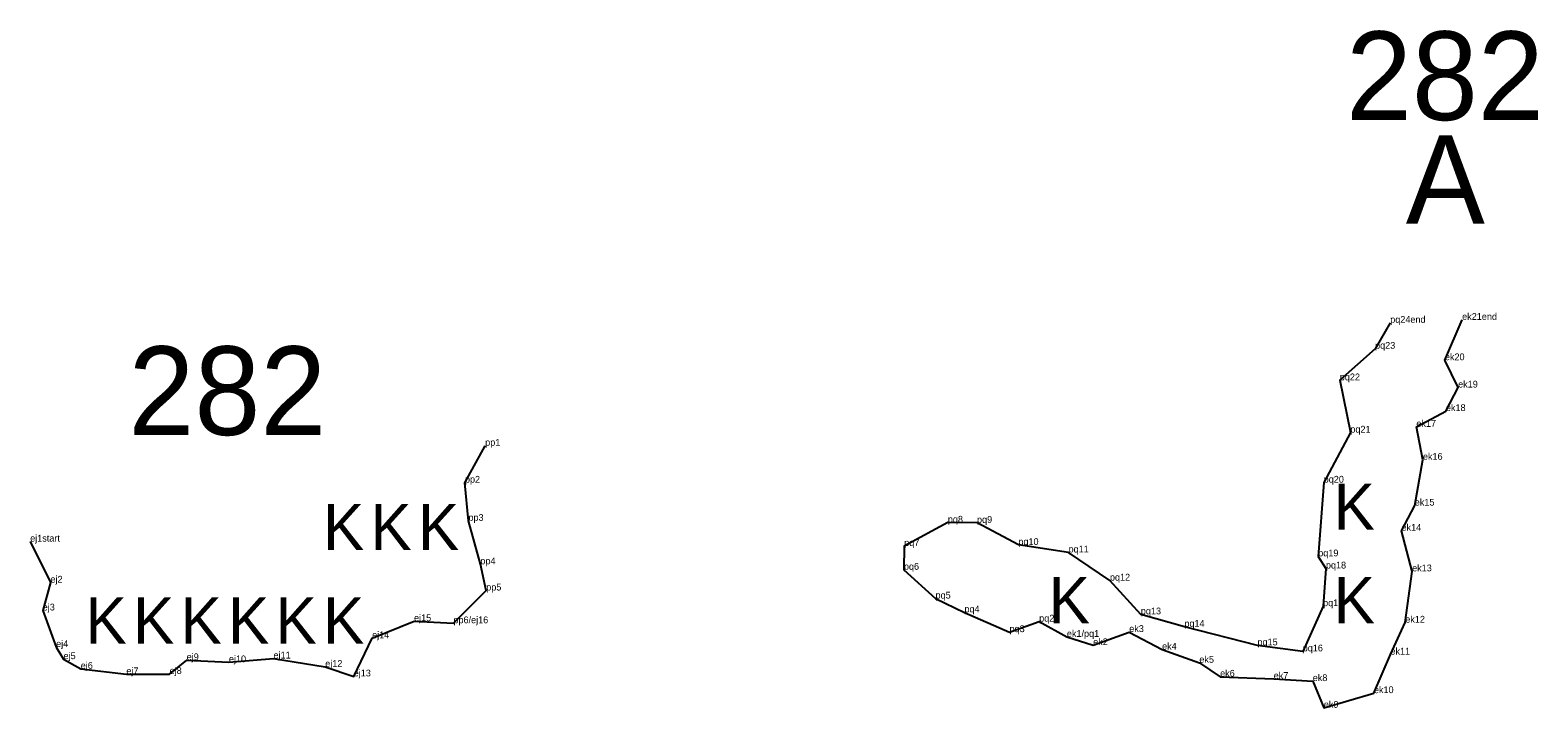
# Model space of a CAD drawing. Extents: x 2072529 to 2268812, y 436423 to 470008.
# Drawn here: x 2242590 to 2243701, y 441089 to 441588 of the extents above; entities that cross this region are included whole.
import ezdxf

# ---------------------------------------------------------------- set-up
doc = ezdxf.new("R2010")
doc.units = 0
for name, color, linetype in [('Old_Level_20', 7, 'Continuous'), ('Old_Level_52', 7, 'Continuous'), ('Old_Level_55', 7, 'Continuous'), ('Old_Level_60', 7, 'Continuous'), ('Old_Level_62', 7, 'Continuous')]:
    doc.layers.add(name, color=color, linetype=linetype)

msp = doc.modelspace()

# ---------------------------------------------------------------- linework, layer by layer
at = {"layer": 'Old_Level_20'}
for p, q in [((2243592.525, 441372.572), (2243592.525, 441372.572)), ((2243645.53, 441374.726), (2243645.53, 441374.726)), ((2243581.368, 441353.449), (2243581.368, 441353.449)), ((2243632.814, 441344.961), (2243632.814, 441344.961)), ((2243555.368, 441330.16), (2243555.368, 441330.16)), ((2243642.57, 441324.819), (2243642.57, 441324.819)), ((2243633.553, 441307.474), (2243633.553, 441307.474)), ((2243563.152, 441291.577), (2243563.152, 441291.577)), ((2243611.773, 441295.836), (2243611.773, 441295.836)), ((2242925.614, 441281.918), (2242925.614, 441281.918)), ((2243616.622, 441271.518), (2243616.622, 441271.518)), ((2242910.696, 441254.655), (2242910.696, 441254.655)), ((2243543.504, 441254.679), (2243543.504, 441254.679)), ((2243610.634, 441237.723), (2243610.634, 441237.723)), ((2242913.263, 441226.493), (2242913.263, 441226.493)), ((2243266.538, 441225.164), (2243266.538, 441225.164)), ((2243288.046, 441224.991), (2243288.046, 441224.991)), ((2242590.314, 441211.19), (2242590.314, 441211.19)), ((2243318.524, 441208.688), (2243318.524, 441208.688)), ((2243600.837, 441219.164), (2243600.837, 441219.164)), ((2243234.395, 441207.91), (2243234.395, 441207.91)), ((2243355.504, 441203.173), (2243355.504, 441203.173)), ((2243539.461, 441200.297), (2243539.461, 441200.297)), ((2242922.074, 441194.465), (2242922.074, 441194.465)), ((2243234.158, 441190.406), (2243234.158, 441190.406)), ((2243545.129, 441191.353), (2243545.129, 441191.353)), ((2243608.673, 441189.245), (2243608.673, 441189.245)), ((2242605.312, 441180.928), (2242605.312, 441180.928)), ((2243385.968, 441182.446), (2243385.968, 441182.446)), ((2242926.383, 441175.137), (2242926.383, 441175.137)), ((2243257.476, 441169.186), (2243257.476, 441169.186)), ((2242599.552, 441160.387), (2242599.552, 441160.387)), ((2243278.798, 441159.002), (2243278.798, 441159.002)), ((2243408.754, 441157.537), (2243408.754, 441157.537)), ((2243543.067, 441163.582), (2243543.067, 441163.582)), ((2242873.198, 441152.511), (2242873.198, 441152.511)), ((2242902.221, 441150.97), (2242902.221, 441150.97)), ((2243312.007, 441144.425), (2243312.007, 441144.425)), ((2243333.847, 441152.189), (2243333.847, 441152.189)), ((2243400.204, 441144.505), (2243400.204, 441144.505)), ((2243440.843, 441148.363), (2243440.843, 441148.363)), ((2243603.621, 441151.408), (2243603.621, 441151.408)), ((2242609.445, 441133.415), (2242609.445, 441133.415)), ((2242842.325, 441139.889), (2242842.325, 441139.889)), ((2243354.261, 441140.909), (2243354.261, 441140.909)), ((2243373.638, 441134.81), (2243373.638, 441134.81)), ((2243424.413, 441131.51), (2243424.413, 441131.51)), ((2243494.697, 441134.645), (2243494.697, 441134.645)), ((2242614.906, 441124.495), (2242614.906, 441124.495)), ((2242705.647, 441123.702), (2242705.647, 441123.702)), ((2242736.778, 441122.189), (2242736.778, 441122.189)), ((2242769.626, 441124.954), (2242769.626, 441124.954)), ((2243451.881, 441121.823), (2243451.881, 441121.823)), ((2243528.043, 441130.221), (2243528.043, 441130.221)), ((2243592.683, 441127.837), (2243592.683, 441127.837)), ((2242627.568, 441117.365), (2242627.568, 441117.365)), ((2242661.201, 441113.359), (2242661.201, 441113.359)), ((2242693.1, 441113.491), (2242693.1, 441113.491)), ((2242807.746, 441118.766), (2242807.746, 441118.766)), ((2242828.732, 441111.767), (2242828.732, 441111.767)), ((2243467.174, 441111.566), (2243467.174, 441111.566)), ((2243506.655, 441109.917), (2243506.655, 441109.917)), ((2243535.453, 441108.301), (2243535.453, 441108.301)), ((2243580.516, 441099.4), (2243580.516, 441099.4)), ((2243543.607, 441088.622), (2243543.607, 441088.622))]:
    msp.add_line(p, q, dxfattribs=at)
at = {"layer": 'Old_Level_52'}
for points in [[(2243592.525, 441372.572), (2243581.368, 441353.449), (2243555.368, 441330.16), (2243563.152, 441291.577), (2243543.504, 441254.679), (2243539.461, 441200.297), (2243545.129, 441191.353), (2243543.067, 441163.582), (2243528.043, 441130.221), (2243494.697, 441134.645), (2243440.843, 441148.363), (2243408.754, 441157.537), (2243385.968, 441182.446), (2243355.504, 441203.173), (2243318.524, 441208.688), (2243288.046, 441224.991), (2243266.538, 441225.164), (2243234.395, 441207.91), (2243234.158, 441190.406), (2243257.476, 441169.186), (2243278.798, 441159.002), (2243312.007, 441144.425), (2243333.847, 441152.189), (2243354.261, 441140.909)], [(2243354.261, 441140.909), (2243373.638, 441134.81), (2243400.204, 441144.505), (2243424.413, 441131.51), (2243451.881, 441121.823), (2243467.174, 441111.566), (2243506.655, 441109.917), (2243535.453, 441108.301), (2243543.607, 441088.622), (2243580.516, 441099.4), (2243592.683, 441127.837), (2243603.621, 441151.408), (2243608.673, 441189.245), (2243600.837, 441219.164), (2243610.634, 441237.723), (2243616.622, 441271.518), (2243611.773, 441295.836), (2243633.553, 441307.474), (2243642.57, 441324.819), (2243632.814, 441344.961), (2243645.53, 441374.726)], [(2242590.314, 441211.19), (2242605.312, 441180.928), (2242599.552, 441160.387), (2242609.445, 441133.415), (2242614.906, 441124.495), (2242627.568, 441117.365), (2242661.201, 441113.359), (2242693.1, 441113.491), (2242705.647, 441123.702), (2242736.778, 441122.189), (2242769.626, 441124.954), (2242807.746, 441118.766), (2242828.732, 441111.767), (2242842.325, 441139.889), (2242873.198, 441152.511), (2242902.221, 441150.97), (2242926.383, 441175.137), (2242922.074, 441194.465), (2242913.263, 441226.493), (2242910.696, 441254.655), (2242925.614, 441281.918)]]:
    msp.add_lwpolyline(points, dxfattribs=at)

# ---------------------------------------------------------------- texts
at = {"layer": 'Old_Level_55'}
for p in [(2243550.877, 441219.972), (2242806.129, 441204.977), (2242841.129, 441204.977), (2242876.129, 441204.977), (2243340.877, 441150.972), (2243550.877, 441150.972), (2242631.129, 441135.977), (2242666.129, 441135.977), (2242701.129, 441135.977), (2242736.129, 441135.977), (2242771.129, 441135.977), (2242806.129, 441135.977)]:
    msp.add_text('K', height=34, dxfattribs=at).set_placement(p)
at = {"layer": 'Old_Level_60'}
for s, p in [('pq24end', (2243592.525, 441372.572)), ('ek21end', (2243645.53, 441374.726)), ('pq23', (2243581.368, 441353.449)), ('ek20', (2243632.814, 441344.961)), ('pq22', (2243555.368, 441330.16)), ('ek19', (2243642.57, 441324.819)), ('ek18', (2243633.553, 441307.474)), ('ek17', (2243611.773, 441295.836)), ('pp1', (2242925.614, 441281.918)), ('pq21', (2243563.152, 441291.577)), ('ek16', (2243616.622, 441271.518)), ('pp2', (2242910.696, 441254.655)), ('pq20', (2243543.504, 441254.679)), ('ek15', (2243610.634, 441237.723)), ('pp3', (2242913.263, 441226.493)), ('pq8', (2243266.538, 441225.164)), ('pq9', (2243288.046, 441224.991)), ('ek14', (2243600.837, 441219.164)), ('ej1start', (2242590.314, 441211.19)), ('pq7', (2243234.395, 441207.91)), ('pq10', (2243318.524, 441208.688)), ('pp4', (2242922.074, 441194.465)), ('pq11', (2243355.504, 441203.173)), ('pq19', (2243539.461, 441200.297)), ('pq6', (2243234.158, 441190.406)), ('pq12', (2243385.968, 441182.446)), ('pq18', (2243545.129, 441191.353)), ('ek13', (2243608.673, 441189.245)), ('ej2', (2242605.312, 441180.928)), ('pp5', (2242926.383, 441175.137)), ('ej3', (2242599.552, 441160.387)), ('pq5', (2243257.476, 441169.186)), ('pq17', (2243543.067, 441163.582)), ('ej15', (2242873.198, 441152.511)), ('pp6/ej16', (2242902.221, 441150.97)), ('pq4', (2243278.798, 441159.002)), ('pq2', (2243333.847, 441152.189)), ('pq13', (2243408.754, 441157.537)), ('pq14', (2243440.843, 441148.363)), ('ek12', (2243603.621, 441151.408)), ('ej14', (2242842.325, 441139.889)), ('pq3', (2243312.007, 441144.425)), ('ek1/pq1', (2243354.261, 441140.909)), ('ek3', (2243400.204, 441144.505)), ('ej4', (2242609.445, 441133.415)), ('ek2', (2243373.638, 441134.81)), ('ek4', (2243424.413, 441131.51)), ('pq15', (2243494.697, 441134.645)), ('pq16', (2243528.043, 441130.221)), ('ek11', (2243592.683, 441127.837)), ('ej5', (2242614.906, 441124.495)), ('ej6', (2242627.568, 441117.365)), ('ej9', (2242705.647, 441123.702)), ('ej10', (2242736.778, 441122.189)), ('ej11', (2242769.626, 441124.954)), ('ej12', (2242807.746, 441118.766)), ('ek5', (2243451.881, 441121.823)), ('ej7', (2242661.201, 441113.359)), ('ej8', (2242693.1, 441113.491)), ('ej13', (2242828.732, 441111.767)), ('ek6', (2243467.174, 441111.566)), ('ek7', (2243506.655, 441109.917)), ('ek8', (2243535.453, 441108.301)), ('ek10', (2243580.516, 441099.4)), ('ek9', (2243543.607, 441088.622))]:
    msp.add_text(s, height=5, dxfattribs=at).set_placement(p)
at = {"layer": 'Old_Level_62'}
for s, p in [('282', (2243559.92, 441522.137)), ('282', (2243559.92, 441522.137)), ('A', (2243603.995, 441445.619)), ('A', (2243603.995, 441445.619)), ('282', (2242662.763, 441289.832))]:
    msp.add_text(s, height=65.34, dxfattribs=at).set_placement(p)

doc.saveas('drawing.dxf')
